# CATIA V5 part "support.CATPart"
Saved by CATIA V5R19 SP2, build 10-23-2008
Part number: Halterplatte
Material "Acier": density 7860 kg/m3, Young's modulus 2e+11 Pa, Poisson ratio 0.266, thermal expansion 1.17e-05 1/K
Bounding box of the stored display mesh (mm): x -290.355 to 0, y 0 to 260.006, z -49.338 to 191.711
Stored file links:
  C:\Documents and Settings\Administrateur\Bureau\support.CATPart
  C:\Program Files\Dassault Systemes\B19\intel_a\startup\materials\French\Catalog.CATMaterial
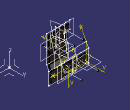
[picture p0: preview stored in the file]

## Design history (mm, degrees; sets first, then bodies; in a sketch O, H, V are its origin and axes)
SheetMetalParameters1: Thickness 6, BendRadius 6, KFactor 0.325257 {= log(min(100,max(20*SheetMetalParameters1.BendRadius,SheetMetalParameters1.Thickness)/SheetMetalParameters1.Thickness))/log(100)/2}, ReliefRadialLength 1, ReliefAxialLength 2, MinimumBendRadius 0
AxisSystem1: origin (0, 0, 0), X (1, 0, 0), Y (0, 1, 0), Z (0, 0, 1)
Set1 "esquisses"
  Sketch1 on Plane5, origin (-180.986, 144.767, -14.723), H (1, 0.0082, 0), V (0, 0.0003, -1)
    line L1 (-109.3721, 34.6145) -> (109.3721, 34.6145)
    line L2 (109.3721, 34.6145) -> (109.3721, -34.6145)
    line L3 (109.3721, -34.6145) -> (-109.3721, -34.6145)
    line L4 (-109.3721, -34.6145) -> (-109.3721, 34.6145)
    length L2 = 69.229
    length L1 = 218.7443
    horizontal: L1 H
    vertical: L2 V, L4 V
    symmetry: L2 L4 V, L3 L1 H
  Sketch2 on Plane11, origin (-290.2426, 130.8884, 44.7061), H (0.9999, 0.0145, 0), V (0, 0.0004, -1)
    line L1 (106.2232, 0) -> (218.74, 0)
    line L2 (218.74, 0) -> (218.74, -147.0045)
    line L3 (218.74, -147.0045) -> (113.0649, -147.0045)
    line L4 (123.9647, -102.0223) -> (106.2232, 0)
    point P2 (218.74, 0)
    reference projected point E1 (218.74, 0) from vertex [element of Sketch3 | element of Sketch3]
    line L5 (123.9647, -102.0223) -> (89.9331, -102.0223)
    line L6 (89.9331, -102.0223) -> (89.9331, -147.0045)
    line L7 (89.9331, -147.0045) -> (113.0649, -147.0045)
    point P7 (89.9331, -147.0045)
    distance L3 L1 = 147.0045
    length L5 = 34.0316
    length L6 = 44.9822
    horizontal: L3 H, L5 H, L7 H
    vertical: L2 V, L6 V
    coincidence: P2 E1, P7 L3
  Sketch3 on Plane10, origin (-290.3544, 143.8581, 19.8915), H (1, 0.0082, 0), V (0.0036, -0.4387, 0.8986)
    line L1 (0, 0) -> (218.7443, 0)
    line L2 (218.7443, 0) -> (218.7443, 27.6139)
    line L3 (218.7443, 27.6139) -> (0, 27.6139)
    line L4 (0, 27.6139) -> (0, 0)
    point P1 (218.7443, 0)
    reference projected point E1 (218.7443, 0) from vertex [element of Sketch1 | element of Sketch1]
    distance L3 L1 = 27.6139
    vertical: L2 V, L4 V
    coincidence: E1 P1
  Sketch4 on Plane8, origin (-183.218, 91.43, 54.956), H (-0.0464, -0.0004, -0.9989), V (0.0082, -1, 0)
    line L1 (-88, 16.2387) -> (10.2607, 16.2387)
    line L2 (10.2607, 16.2387) -> (10.2607, -41.0015)
    line L3 (10.2607, -41.0015) -> (-88, -41.0015)
    line L4 (-88, -41.0015) -> (-88, 16.2387)
    point P3 (10.2607, -41.0015)
    reference projected point E1 (10.2607, -41.0015) from vertex [element of Sketch2 | element of Sketch2]
    distance L3 L1 = 57.2402
    distance V L4 = 88
    horizontal: L1 H
    vertical: L4 V, L2 V
    coincidence: P3 E1
Set2 "plans"
  Point1 "Punkt 1 achse 1": (-154, 151.694, -15.701), in AxisSystem1
  Point2 "Punkt 2 achse 1": (-155.303, 241.691, -15.666), in AxisSystem1
  Line1: type PtPt, FirstPoint Point1, SecondPoint Point2
  Point3 "Laufpunkt 1": type OnCurve, Support Line1, Length 90.0064
  Plane1: type Normal, Curve Line1, RefPoint Point3
  Point4 "Punkt 1 achse2": (-243.713, 150.964, -15.137), in AxisSystem1
  Point5 "Punkt 2 achse 2": (-244.449, 240.961, -15.103), in AxisSystem1
  Line2: type PtPt, FirstPoint Point4, SecondPoint Point5
  Point6 "Laufpunkt 2": type OnCurve, Support Line2, Length 90
  Plane2: type Normal, Curve Line2, RefPoint Point6
  Point7 "Punkt  1 achse 3": (-173.708, 141.47, 160.075), in AxisSystem1
  Point8 "Punkt  2 achse  3": (-174.444, 231.467, 160.109), in AxisSystem1
  Line3: type PtPt, FirstPoint Point7, SecondPoint Point8
  Point9 "Laufpunkt 3": type OnCurve, Support Line3, Length 90
  Plane3: type Normal, Curve Line3, RefPoint Point9
  Point10 "Punkt 1 achse 4": (-121.71, 141.896, 158.325), in AxisSystem1
  Point11 "Punkt 2 achse 4": (-122.446, 231.893, 158.359), in AxisSystem1
  Line4: type PtPt, FirstPoint Point10, SecondPoint Point11
  Point12 "Laufpunkt 4": type OnCurve, Support Line4, Length 90
  Plane4: type Normal, Curve Line4, RefPoint Point12
  Point13 "Punkt 1 achse 5": (-180.822, 124.767, -14.73), in AxisSystem1
  Point14 "Punkt 2 achse 5": (-180.986, 144.767, -14.723), in AxisSystem1
  Line5: type PtPt, FirstPoint Point14, SecondPoint Point13
  Point15 "Laufpunkt achse 5": type OnCurve, Support Line5, Length 20.0007
  Plane5: type Normal, Curve Line5, RefPoint Point15
  Point16 "Punkt 1 achse 6": (-92.617, 142.338, -9.318), in AxisSystem1
  Point17 "Punkt 2 achse 6": (-92.643, 145.488, -9.317), in AxisSystem1
  Line6: type PtPt, FirstPoint Point17, SecondPoint Point16
  Point18 "Laufpunkt achse 6": type OnCurve, Support Line6, Length 3.1501
  Plane6: type Normal, Curve Line6, RefPoint Point18
  Point19 "Punkt 1 achse 7": (-95.854, 91.358, 100.45), in AxisSystem1
  Point20 "Punkt 2 achse 7": (-95.854, 116.358, 100.45), in AxisSystem1
  Line7: type PtPt, FirstPoint Point19, SecondPoint Point20
  Point21 "Laufpunkt achse 7": type OnCurve, Support Line7, Length 25
  Plane7: type Normal, Curve Line7, RefPoint Point21
  Point22 "Punkt 1 achse 8": (-158.345, 91.634, 53.8), in AxisSystem1
  Point23 "Punkt 2 achse 8": (-183.218, 91.43, 54.956), in AxisSystem1
  Line8: type PtPt, FirstPoint Point22, SecondPoint Point23
  Point24 "Laufpunkt 8": type OnCurve, Support Line8, Length 24.9007
  Plane8: type Normal, Curve Line8, RefPoint Point24
  Point25 "Punkt 1 achse  9": (-147.28, 100.21, 131.869), in AxisSystem1
  Point26 "Punkt 2 achse 9": (-172.152, 100.006, 133.025), in AxisSystem1
  Line9: type PtPt, FirstPoint Point26, SecondPoint Point25
  Point27 "Laufpunkt achse 9": type OnCurve, Support Line9, Length 24.8997
  Plane9: type Normal, Curve Line9, RefPoint Point27
Set3 "origin"
  Point28: (0, 0, 0), in AxisSystem1
Set4 "geometrie d aide"
  Plane10: type Angle, RefPlane Plane5, Direction Sketch1.L3, Angle 26
  Plane11: type Angle, RefPlane Plane1, Direction Sketch3.L3, Angle 0
  Point29 "point application poids": (-164.152, 260.006, 75.025), in AxisSystem1
  Plane12: type OffsetPt, RefPlane xy-plane, RefPoint Point29
Body1 (main body), material "Acier"
  Wall1: Thickness 6, Profile Sketch1
  Wall2: Thickness 6, Profile Sketch3
  Wall3: Thickness 6, Profile Sketch2
  Wall4: Thickness 6, Profile Sketch4
  d_Bend1: Bend_BendTable SheetMetalParameters1, Bend_Thickness 6, Bend_KFactor 0.325257 {= log(min(100,max(20*d_Bend1.Bend_KFactorRadius,SheetMetalParameters1.Thickness)/SheetMetalParameters1.Thickness))/log(100)/2}, Bend_FirstSupport Wall2, Bend_SecondSupport Wall1, Bend_KFactorRadius 6 {= d_Bend1.CylindricalBendSurf_Radius}, Bend_Deduction -1.9325 {= (d_Bend1.CylindricalBendSurf_Radius+SheetMetalParameters1.Thickness*d_Bend1.Bend_KFactor)*(PI-abs(d_Bend1.BendSurf_OpenAngle))-2*(d_Bend1.CylindricalBendSurf_Radius+SheetMetalParameters1.Thickness)*tan(min((PI-abs(d_Bend1.BendSurf_OpenAngle)),(PI/2))/2)}
  d_Bend2: Bend_BendTable SheetMetalParameters1, Bend_Thickness 6, Bend_KFactor 0.325257 {= log(min(100,max(20*d_Bend2.Bend_KFactorRadius,SheetMetalParameters1.Thickness)/SheetMetalParameters1.Thickness))/log(100)/2}, Bend_FirstSupport Wall3, Bend_SecondSupport Wall4, Bend_KFactorRadius 6 {= d_Bend2.CylindricalBendSurf_Radius}, Bend_Deduction -11.4093 {= (d_Bend2.CylindricalBendSurf_Radius+SheetMetalParameters1.Thickness*d_Bend2.Bend_KFactor)*(PI-abs(d_Bend2.BendSurf_OpenAngle))-2*(d_Bend2.CylindricalBendSurf_Radius+SheetMetalParameters1.Thickness)*tan(min((PI-abs(d_Bend2.BendSurf_OpenAngle)),(PI/2))/2)}
  d_Bend3: Bend_BendTable SheetMetalParameters1, Bend_Thickness 6, Bend_KFactor 0.325257 {= log(min(100,max(20*d_Bend3.Bend_KFactorRadius,SheetMetalParameters1.Thickness)/SheetMetalParameters1.Thickness))/log(100)/2}, Bend_FirstSupport Wall2, Bend_SecondSupport Wall3, Bend_KFactorRadius 6 {= d_Bend3.CylindricalBendSurf_Radius}, Bend_Deduction -1.9325 {= (d_Bend3.CylindricalBendSurf_Radius+SheetMetalParameters1.Thickness*d_Bend3.Bend_KFactor)*(PI-abs(d_Bend3.BendSurf_OpenAngle))-2*(d_Bend3.CylindricalBendSurf_Radius+SheetMetalParameters1.Thickness)*tan(min((PI-abs(d_Bend3.BendSurf_OpenAngle)),(PI/2))/2)}
  CutOut1: Direction Sketch15, EndLimit through (limit type 2), Orientation true, Profile Sketch15, StartLimit through (limit type 2)
  Corner1: CornerRadius 10, CornerChamferEdges (edge [face of CutOut1 | face of CutOut1]; edge [face of CutOut1 | face of CutOut1]; edge [face of CutOut1 | face of CutOut1])
  Chamfer1: ChamferAngle 45, ChamferLength1 1, ChamferLength2 3, ChamferPropagation 2, ChamferReverse false, ChamferType 1, CornerChamferEdges edge [face of CutOut1 | face of Wall3]
  Sketch5 on face of Wall1, origin (-154.2921, 144.9851, -12.4696), H (1, 0.0082, 0), V (0, -0.0003, 1)
    point P1 (0, 0)
  Hole1: placed by Sketch5, at (-154.2921, 144.9851, -12.4696) direction (-0.0082, 1, 0.0003), diameter 10, depth 10, V-bottom angle 120
  Sketch6 on face of Wall1, origin (-180.986, 144.767, -14.723), H (1, 0.0082, 0), V (0, -0.0003, 1)
    point P1 (0, 0)
    reference projected point E1 (0, 0) from Point15
    coincidence: E1 P1
  Hole2: placed by Sketch6, at (-180.986, 144.767, -14.723) direction (-0.0082, 1, 0.0003), diameter 10, depth 10, V-bottom angle 120
  Sketch7 on face of Wall1, origin (-92.643, 145.4895, -9.317), H (1, 0.0082, 0), V (0, -0.0003, 1)
    point P1 (0, 0)
    reference projected point E1 (0, 0) from Point18
    coincidence: E1 P1
  Hole3: placed by Sketch7, at (-92.643, 145.4895, -9.317) direction (-0.0083, 1, 0.0003), diameter 10, depth 10, V-bottom angle 120
  Sketch8 on face of Wall1, origin (-247.1463, 144.2242, -14.0334), H (1, 0.0082, 0), V (0, -0.0003, 1)
    point P1 (0, 0)
  Hole4: placed by Sketch8, at (-247.1463, 144.2242, -14.0334) direction (-0.0082, 1, 0.0003), diameter 10, depth 10, V-bottom angle 120
  Sketch9 on face of Wall3, origin (-90.2534, 133.765, 93.3813), H (0.9999, 0.0145, 0), V (0, -0.0004, 1)
    point P1 (0, 0)
  Hole5: placed by Sketch9, at (-90.2534, 133.765, 93.3813) direction (-0.0145, 0.9999, 0.0004), diameter 10, depth 10, V-bottom angle 120
  Sketch10 on face of Wall3, origin (-128.7191, 133.1818, 160.9915), H (0.9999, 0.0145, 0), V (0, -0.0004, 1)
    point P1 (0, 0)
  Hole6: placed by Sketch10, at (-128.7191, 133.1818, 160.9915) direction (-0.0145, 0.9999, 0.0004), diameter 10, depth 10, V-bottom angle 120
  Sketch11 on face of Wall3, origin (-179.69, 132.4434, 162.1322), H (0.9999, 0.0145, 0), V (0, -0.0004, 1)
    point P1 (0, 0)
  Hole7: placed by Sketch11, at (-179.69, 132.4434, 162.1322) direction (-0.0145, 0.9999, 0.0004), diameter 10, depth 10, V-bottom angle 120
  Sketch12 on face of Wall4, origin (-185.4516, 95.8543, 136.9205), H (0.0471, -0.1736, 0.9837), V (0, 0.9848, 0.1738)
    point P1 (0, 0)
  Hole8: placed by Sketch12, at (-185.4516, 95.8543, 136.9205) direction (0.9989, 0.0082, -0.0464), diameter 10, depth 10, V-bottom angle 120
  Sketch13 on face of Wall4, origin (-188.8151, 89.9258, 63.5036), H (0.0471, -0.1736, 0.9837), V (0, 0.9848, 0.1738)
    point P1 (0, 0)
  Hole9: placed by Sketch13, at (-188.8151, 89.9258, 63.5036) direction (0.9989, 0.0082, -0.0464), diameter 10, depth 10, V-bottom angle 120
  Corner2: CornerRadius 10, CornerChamferEdges edge [face of CutOut1 | face of Wall3]
  Sketch14 on Plane12, origin (-164.152, 260.006, 75.025), H (1, 0, 0), V (0, 1, 0)
    circle A1 centre (0, 0) radius 2.1437
  Sketch15 on Plane1, origin (-154, 151.694, -15.701), H (-0.9999, -0.0145, 0), V (0, -0.0004, 1)
    line L1 (38.192, 198.3768) -> (-71.367, 198.3768)
    line L2 (-71.367, 198.3768) -> (-76.8558, -25.9743)
    point P3 (-76.8558, -25.9743)
    point P4 (-76.8558, -25.9743)
    line L3 (-76.8558, -25.9743) -> (121.9276, -25.9743)
    line L4 (121.9276, -25.9743) -> (121.9276, 23.3401)
    line L5 (121.9276, 23.3401) -> (38.8382, 25.3729)
    line L6 (38.8382, 25.3729) -> (21.1318, 25.3729)
    line L7 (21.1318, 25.3729) -> (21.1318, 69.1975)
    line L8 (21.1318, 69.1975) -> (83.1472, 69.1975)
    line L9 (83.1472, 69.1975) -> (85.3501, 159.241)
    line L10 (85.3501, 159.241) -> (38.192, 159.241)
    line L11 (38.192, 159.241) -> (38.192, 198.3768)
    horizontal: L1 H, L3 H, L6 H, L8 H, L10 H
    vertical: L4 V, L7 V, L11 V
    perpendicularity: L5 L2
    parallelism: L9 L2
    coincidence: P3 P4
